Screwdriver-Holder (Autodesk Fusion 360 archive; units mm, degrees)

design "Screwdriver-Holder" references "Base"
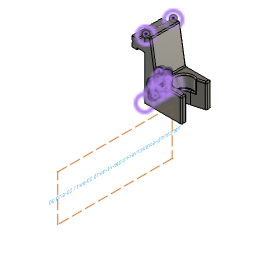
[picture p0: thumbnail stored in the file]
parameter "back_width_min" = 5
parameter "back_width_max" = 10
parameter "width" = 25 (= "screwdriver_handle_width + 10 mm")
parameter "height" = 50
parameter "bottom_height" = 10
parameter "screwdriver_handle_width" = 15
parameter "screwdriver_stick_width" = 11
parameter "pull_out_tolerance" = 3
parameter "screwdriver_inset" = 10
parameter "handle_padding" = 3
sketch "Back" plane through (0, 0, 0) normal (1, 0, 0) x axis (0, 1, 0)
  line L1 (25, 0) -> (0, 0)
  line L2 (25, 50) -> (25, 0)
  line L3 (0, 50) -> (25, 50)
  line L4 (0, 0) -> (0, 50)
  point P1 (0, 0)
  point P2 (0, 0)
  point P3 (25, 0)
  point P5 (0, 50)
  horizontal L1
  vertical L2
  horizontal L3
  vertical L4
  coincident P1 P2
  dimension "d5" distance P2 P3 = 25 (= "width")
  dimension "d6" distance P2 P5 = 50 (= "height")
extrude "Extrude1" new body sketch "Back" along normal blind 10 (= "back_width_max")
sketch "Bottom" plane through (10, 0, 0) normal (1, 0, 0) x axis (0, 1, 0)
  line L1 (0, 0) -> (0, 50)
  line L2 (25, 0) -> (0, 0)
  line L3 (25, 50) -> (25, 0)
  line L4 (0, 50) -> (25, 50)
  line L5 (25, 50) -> (25, 0)
  line L6 (25, 10) -> (25, 0)
  line L7 (25, 20) -> (25, 10)
  line L8 (0, 20) -> (25, 20)
  point P4 (25, 0)
  point P8 (25, 0)
  point P11 (0, 20)
  point P9 (25, 10)
  point P10 (25, 20)
  coincident P4 P8
  perpendicular L2 L6
  parallel L5 L7
  coincident L1 P11
  perpendicular L1 L8
  dimension "d14" distance P8 P9 = 10 (= "screwdriver_inset")
  dimension "d15" distance P9 P10 = 10 (= "bottom_height")
extrude "Extrude2" add sketch "Bottom" + "Sketch4" profile of S1:L1 S1:L2 S1:L3 S1:L5 S1:L8 blind 21 (= "screwdriver_handle_width + handle_padding + pull_out_tolerance")
sketch "Holes" plane through (0, 0, 20) normal (0, 0, 1) x axis (-1, 0, 0)
  line L1 (-10, 0) -> (-10, -25)
  line L2 (-31, 0) -> (-10, 0)
  line L3 (-31, -25) -> (-31, 0)
  line L4 (-10, -25) -> (-31, -25)
  line L5 (-31, -25) -> (-10, 0)
  line L6 (-20.5, -25) -> (-20.5, 0)
  line L7 (-31, -7) -> (-20.5, -7)
  line L8 (-31, -18) -> (-20.5, -18)
  line L9 (-31, -4) -> (-31, -7)
  line L10 (-31, -21) -> (-31, -18)
  line L11 (-31, -21) -> (-20.5, -18)
  line L12 (-31, -4) -> (-20.5, -7)
  circle C1 centre (-20.5, -12.5) radius 7.5
  circle C2 centre (-20.5, -12.5) radius 5.5
  point P3 (-10, 0)
  point P6 (-10, 0)
  point P5 (-31, -25)
  point P7 (-31, -25)
  point P8 (-20.5, -12.5)
  point P10 (-20.5, 0)
  point P11 (-20.5, -25)
  point P12 (-20.5, -7)
  point P13 (-31, -7)
  point P14 (-20.5, -18)
  point P15 (-31, -18)
  point P16 (-31, -4)
  point P17 (-31, -21)
  coincident P3 P6
  coincident P5 P7
  midpoint L5 P8
  concentric C1 C2
  midpoint L2 P10
  midpoint L4 P11
  coincident C2 P12
  coincident L6 P12
  coincident L3 P13
  tangent C2 L7
  coincident L6 P14
  coincident C2 P14
  coincident L3 P15
  tangent C2 L8
  perpendicular L7 L9
  perpendicular L8 L10
  dimension "d19" diameter C1 = 15 (= "screwdriver_handle_width")
  dimension "d20" diameter C2 = 11 (= "screwdriver_stick_width")
  dimension "d25" distance P13 P16 = 3 (= "handle_padding")
  dimension "d26" distance P15 P17 = 3 (= "handle_padding")
extrude "Extrude3" cut sketch "Holes" + "Sketch4" profile of S1:L3 S1:C1 S1:C2 S1:L7 S1:L8 blind -2000
extrude "Extrude4" cut sketch "Holes" + "Sketch4" profile of S1:C1 S1:C2 S1:L7 S1:L8 no distance stored
component_insert "Component Insert"
move "Move1" sketch "Sketch4"
move "Move3" sketch "Sketch4"
move "Move4" sketch "Sketch4"
position "Position1"
sketch "Sketch4" plane through (0, 37.5, 0) normal (0, 1, 0) x axis (-1, 0, 0)
  line L1 (-9.6118, 60) -> (-9.6118, 10)
  line L2 (-19.6118, 60) -> (-9.6118, 60)
  line L3 (-19.6118, 30) -> (-19.6118, 60)
  line L4 (-9.6118, 10) -> (-40.6118, 10)
  line L5 (-14.6118, 60) -> (-9.6118, 60)
  line L6 (-19.6118, 30) -> (-14.6118, 60)
  line L7 (-40.6118, 30) -> (-19.6118, 30)
  line L8 (-40.6118, 10) -> (-40.6118, 30)
  point P3 (-9.6118, 60)
  point P7 (-9.6118, 60)
  point P5 (-19.6118, 30)
  point P9 (-19.6118, 30)
  point P8 (-14.6118, 60)
  coincident P3 P7
  perpendicular L1 L5
  coincident P5 P9
  dimension "d27" distance P7 P8 = 5 (= "back_width_min")
extrude "Extrude5" cut sketch "Sketch4" profile of L2 L3 L6 against normal blind 1000
fillet "Fillet1" radius 1
sketch "Text" plane through (9.6118, 0, 0) normal (-1, 0, 0) x axis (0, -1, 0)
  line L1 (-37.5, 10) -> (-37.5, 59)
  line L2 (-12.5, 10) -> (-37.5, 10)
  line L3 (-12.5, 59) -> (-12.5, 10)
  line L4 (-36.5, 60) -> (-13.5, 60)
  line L5 (-37.5, 29) -> (-12.5, 29)
  line L6 (-37.5, 10) -> (-37.5, 29)
  line L7 (-12.5, 10) -> (-37.5, 10)
  line L8 (-12.5, 29) -> (-12.5, 10)
  line L9 (-12.5, 19.5) -> (-37.5, 19.5)
  curve K1
  curve K2
  curve K3
  curve K4
  arc A1 centre (-36.5, 59) radius 1 clockwise from (-37.5, 59) to (-36.5, 60)
  arc A2 centre (-13.5, 59) radius 1 clockwise from (-13.5, 60) to (-12.5, 59)
  point P4 (-37.5, 10)
  point P11 (-37.5, 10)
  point P8 (-12.5, 29)
  point P9 (-12.5, 29)
  point P13 (-37.5, 19.5)
  point P14 (-12.5, 19.5)
  horizontal L5
  vertical L6
  horizontal L7
  vertical L8
  coincident P4 P11
  coincident P8 P9
  midpoint L6 P13
  midpoint L8 P14
  coincident P8
  coincident P4
  coincident P14
  dimension "d39" Text1-Height = 3
extrude "Extrude12" cut sketch "Text" + "Sketch4" blind -2
sketch "File name" plane through (9.6118, 0, 0) normal (-1, 0, 0) x axis (0, -1, 0)
  line L1 (-37.5, 10) -> (-37.5, 59)
  line L2 (-12.5, 10) -> (-37.5, 10)
  line L3 (-12.5, 59) -> (-12.5, 10)
  curve K1
  curve K2
  curve K3
  curve K4
  line L4 (-36.5, 60) -> (-13.5, 60)
  line L5 (-26.0273, 25.0232) -> (-25.2046, 27.1965)
  line L6 (-26.3711, 25.0232) -> (-26.0273, 25.0232)
  line L7 (-27.1978, 27.1965) -> (-26.3711, 25.0232)
  line L8 (-26.809, 27.1965) -> (-27.1978, 27.1965)
  line L9 (-26.3424, 25.895) -> (-26.809, 27.1965)
  curve K5 (-26.2033, 25.457) -> (-26.3424, 25.895)
  curve K6 (-26.0662, 25.8704) -> (-26.2033, 25.457)
  line L10 (-25.5832, 27.1965) -> (-26.0662, 25.8704)
  line L11 (-25.2046, 27.1965) -> (-25.5832, 27.1965)
  line L12 (-32.3158, 20.3411) -> (-32.3158, 21.53)
  line L13 (-32.6842, 20.3411) -> (-32.3158, 20.3411)
  line L14 (-32.6842, 23.3411) -> (-32.6842, 20.3411)
  line L15 (-32.3158, 23.3411) -> (-32.6842, 23.3411)
  line L16 (-32.3158, 22.2647) -> (-32.3158, 23.3411)
  curve K7 (-31.6651, 22.5634) -> (-32.3158, 22.2647)
  curve K8 (-31.2456, 22.4673) -> (-31.6651, 22.5634)
  curve K9 (-30.9918, 22.2053) -> (-31.2456, 22.4673)
  curve K10 (-30.9141, 21.7183) -> (-30.9918, 22.2053)
  line L17 (-30.9141, 20.3411) -> (-30.9141, 21.7183)
  line L18 (-31.2824, 20.3411) -> (-30.9141, 20.3411)
  line L19 (-31.2824, 21.7183) -> (-31.2824, 20.3411)
  curve K11 (-31.4031, 22.1194) -> (-31.2824, 21.7183)
  curve K12 (-31.7408, 22.2462) -> (-31.4031, 22.1194)
  curve K13 (-32.0498, 22.1603) -> (-31.7408, 22.2462)
  curve K14 (-32.2544, 21.9311) -> (-32.0498, 22.1603)
  curve K15 (-32.3158, 21.53) -> (-32.2544, 21.9311)
  line L20 (-26.0416, 23.3533) -> (-26.279, 23.3533)
  line L21 (-26.0416, 20.3411) -> (-26.0416, 23.3533)
  line L22 (-26.41, 20.3411) -> (-26.0416, 20.3411)
  line L23 (-26.41, 22.6883) -> (-26.41, 20.3411)
  line L24 (-27.1467, 22.6003) -> (-27.1467, 22.2442)
  line L25 (-26.5276, 15.6589) -> (-26.1593, 15.6589)
  line L26 (-26.5276, 18.0061) -> (-26.5276, 15.6589)
  line L27 (-28.8155, 15.6589) -> (-28.4328, 15.6589)
  line L28 (-29.1613, 16.9604) -> (-28.8155, 15.6589)
  line L29 (-29.2452, 17.3308) -> (-29.1613, 16.9604)
  line L30 (-29.6852, 15.6589) -> (-29.2452, 17.3308)
  curve K16 (-30.8046, 13.1992) -> (-31.1238, 13.1542)
  curve K17 (-30.3564, 13.1255) -> (-30.8046, 13.1992)
  curve K18 (-31.2875, 12.0737) -> (-30.7248, 11.8977)
  curve K19 (-31.5249, 12.2804) -> (-31.2875, 12.0737)
  curve K20 (-31.6047, 12.573) -> (-31.5249, 12.2804)
  curve K21 (-31.5392, 12.8411) -> (-31.6047, 12.573)
  curve K22 (-31.3571, 13.0477) -> (-31.5392, 12.8411)
  curve K23 (-31.1238, 13.1542) -> (-31.3571, 13.0477)
  curve K24 (-21.7902, 13.9891) -> (-22.3346, 13.8131)
  curve K25 (-21.3666, 13.8909) -> (-21.7902, 13.9891)
  curve K26 (-20.8796, 13.1644) -> (-21.0658, 13.6105)
  curve K27 (-24.561, 13.6105) -> (-24.8619, 13.8909)
  curve K28 (-24.3748, 13.1644) -> (-24.561, 13.6105)
  curve K29 (-25.8298, 13.8131) -> (-26.1552, 13.3117)
  curve K30 (-25.2855, 13.9891) -> (-25.8298, 13.8131)
  curve K31 (-24.8619, 13.8909) -> (-25.2855, 13.9891)
  curve K32 (-17.6872, 18.2926) -> (-17.9881, 18.573)
  curve K33 (-17.501, 17.8465) -> (-17.6872, 18.2926)
  curve K34 (-17.4335, 17.1385) -> (-17.501, 17.8465)
  curve K35 (-17.542, 16.2851) -> (-17.4335, 17.1385)
  curve K36 (-17.8673, 15.7838) -> (-17.542, 16.2851)
  curve K37 (-18.4117, 15.6078) -> (-17.8673, 15.7838)
  curve K38 (-24.3932, 18.2701) -> (-24.9335, 17.9181)
  curve K39 (-24.0658, 18.6712) -> (-24.3932, 18.2701)
  curve K40 (-21.6122, 17.9939) -> (-21.7207, 17.1385)
  curve K41 (-21.2868, 18.4952) -> (-21.6122, 17.9939)
  curve K42 (-31.4042, 17.8076) -> (-31.8523, 17.8813)
  curve K43 (-31.1177, 17.6071) -> (-31.4042, 17.8076)
  curve K44 (-30.9908, 17.2715) -> (-31.1177, 17.6071)
  curve K45 (-31.4942, 17.4843) -> (-31.351, 17.2224)
  curve K46 (-32.1879, 17.4945) -> (-31.8257, 17.5784)
  curve K47 (-32.2964, 17.2981) -> (-32.1879, 17.4945)
  curve K48 (-32.2514, 17.1692) -> (-32.2964, 17.2981)
  curve K49 (-32.1102, 17.0709) -> (-32.2514, 17.1692)
  curve K50 (-31.7848, 16.9768) -> (-32.1102, 17.0709)
  curve K51 (-30.9969, 16.6126) -> (-31.2404, 16.8049)
  curve K52 (-30.9089, 16.2974) -> (-30.9969, 16.6126)
  curve K53 (-31.0174, 15.9495) -> (-30.9089, 16.2974)
  curve K54 (-31.3264, 15.6978) -> (-31.0174, 15.9495)
  curve K55 (-32.4314, 15.7858) -> (-31.7848, 15.6098)
  curve K56 (-32.7138, 16.3076) -> (-32.4314, 15.7858)
  curve K57 (-20.2012, 23.2551) -> (-20.6248, 23.3533)
  curve K58 (-24.0423, 22.3301) -> (-24.6091, 22.1419)
  curve K59 (-23.1091, 21.3581) -> (-23.3793, 22.058)
  curve K60 (-23.3465, 20.6542) -> (-23.1091, 21.3581)
  curve K61 (-24.1344, 20.2899) -> (-23.3465, 20.6542)
  curve K62 (-24.8035, 20.5191) -> (-24.1344, 20.2899)
  curve K63 (-21.4945, 22.676) -> (-21.603, 21.8206)
  curve K64 (-21.1692, 23.1774) -> (-21.4945, 22.676)
  curve K65 (-20.6248, 23.3533) -> (-21.1692, 23.1774)
  line L31 (-24.7115, 21.1596) -> (-25.0982, 21.1269)
  curve K66 (-24.4618, 21.9229) -> (-24.1405, 22.0048)
  line L32 (-29.5675, 20.3411) -> (-29.1276, 22.013)
  line L33 (-29.9523, 20.3411) -> (-29.5675, 20.3411)
  line L34 (-30.6173, 22.5143) -> (-29.9523, 20.3411)
  line L35 (-30.2367, 22.5143) -> (-30.6173, 22.5143)
  line L36 (-29.8909, 21.2599) -> (-30.2367, 22.5143)
  line L37 (-29.7619, 20.7933) -> (-29.8909, 21.2599)
  curve K67 (-29.6494, 21.2415) -> (-29.7619, 20.7933)
  line L38 (-29.3035, 22.5143) -> (-29.6494, 21.2415)
  line L39 (-28.925, 22.5143) -> (-29.3035, 22.5143)
  line L40 (-28.5996, 21.2538) -> (-28.925, 22.5143)
  line L41 (-28.4911, 20.8383) -> (-28.5996, 21.2538)
  line L42 (-28.3663, 21.2578) -> (-28.4911, 20.8383)
  line L43 (-27.9939, 22.5143) -> (-28.3663, 21.2578)
  line L44 (-27.6357, 22.5143) -> (-27.9939, 22.5143)
  line L45 (-28.3151, 20.3411) -> (-27.6357, 22.5143)
  line L46 (-28.6978, 20.3411) -> (-28.3151, 20.3411)
  line L47 (-29.0437, 21.6426) -> (-28.6978, 20.3411)
  line L48 (-29.1276, 22.013) -> (-29.0437, 21.6426)
  line L49 (-23.5941, 28.0355) -> (-23.8315, 28.0355)
  line L50 (-23.5941, 25.0232) -> (-23.5941, 28.0355)
  line L51 (-23.9625, 25.0232) -> (-23.5941, 25.0232)
  line L52 (-23.9625, 27.3704) -> (-23.9625, 25.0232)
  curve K68 (-24.3124, 27.1166) -> (-23.9625, 27.3704)
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  dimension "d57" Text1-Height = 3
extrude "Extrude17" new body of existing geometry blind 1
extrude "Extrude18" add sketch "Sketch4" to an object
extrude "Extrude21" cut sketch "Sketch4" to an object
extrude "Extrude22" add sketch "Sketch4" to an object
extrude "Extrude24" cut sketch "Sketch4" to an object
extrude "Extrude25" add sketch "Sketch4" to an object
extrude "Extrude26" cut sketch "Sketch4" to an object

design "Base"
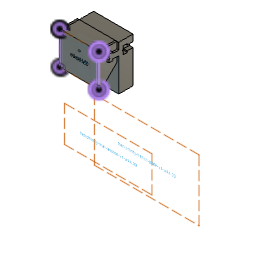
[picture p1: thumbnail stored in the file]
parameter "wall_anchor_height" = 60
parameter "wall_anchor_width" = 20
parameter "wall_anchor_angle" = 45
parameter "width_per_slot" = 40
parameter "slot_inner_width" = 8.5
parameter "slot_inner_height" = 4.5
parameter "slot_outer_width" = 5.6
parameter "slot_outer_height" = 6.5
parameter "slot_dept" = 15
parameter "print_tolerance" = 0.12
parameter "base_plate_thickness" = 16
parameter "base_plate_slot_height" = 50
parameter "wall_anchor_angle_rounded_border" = 1.5
parameter "base_plate_screw_hole_diameter" = 4
parameter "base_plate_screw_head_diameter" = 8
parameter "base_plate_screw_head_height" = 4
parameter "base_plate_screw_hole_side_distance" = 7
parameter "slot_screw_head_width" = 4.42 (= "4.3 mm + print_tolerance")
parameter "slot_screw_thread_width" = 2.12 (= "2 mm + print_tolerance")
parameter "slot_screw_head_height" = 2.12 (= "2 mm + print_tolerance")
parameter "width" = 44
parameter "filament_hole_width" = 1.7
sketch "Side" plane through (0, 0, 0) normal (1, 0, 0) x axis (0, 1, 0)
  line L1 (39.6118, 0) -> (19.6118, 0)
  line L2 (39.6118, 60) -> (39.6118, 0)
  line L3 (19.6118, 60) -> (39.6118, 60)
  line L4 (19.6118, 0) -> (19.6118, 60)
  line L5 (39.6118, 39.6118) -> (0, 0)
  line L6 (56.0196, 0) -> (0, 0)
  point P1 (0, 0)
  point P6 (0, 0)
  point P7 (39.6118, 39.6118)
  point P2 (19.6118, 0)
  point P3 (39.6118, 0)
  point P5 (19.6118, 60)
  horizontal L1
  vertical L2
  horizontal L3
  vertical L4
  horizontal L6
  coincident P1 P6
  coincident L2 P7
  dimension "d4" distance P2 P3 = 20 (= "wall_anchor_width")
  dimension "d5" distance P2 P5 = 60 (= "wall_anchor_height")
  dimension "d6" angle L5 L6 = 45 (= "wall_anchor_angle")
extrude "Extrude1" new body sketch "Side" profile of L1 L2 L3 L4 L5 along normal blind 40 (= "width_per_slot")
sketch "Slot LeftToRight" plane through (0, 0, 0) normal (-1, 0, 0) x axis (0, -1, 0)
  line L1 (-19.6118, 60) -> (-19.6118, 19.6118)
  line L2 (-39.6118, 60) -> (-19.6118, 60)
  line L3 (-39.6118, 39.6118) -> (-39.6118, 60)
  line L4 (-19.6118, 19.6118) -> (-39.6118, 39.6118)
  line L5 (-39.6118, 52.6059) -> (-39.6118, 49.8059)
  line L6 (-39.6118, 47.0059) -> (-39.6118, 49.8059)
  line L7 (-33.1118, 52.6059) -> (-39.6118, 52.6059)
  line L8 (-28.6118, 49.8059) -> (-39.6118, 49.8059)
  line L9 (-28.6118, 54.0559) -> (-28.6118, 49.8059)
  line L10 (-33.1118, 54.0559) -> (-28.6118, 54.0559)
  line L11 (-33.1118, 52.6059) -> (-33.1118, 54.0559)
  line L12 (-28.6118, 45.5559) -> (-28.6118, 49.8059)
  line L13 (-33.1118, 45.5559) -> (-28.6118, 45.5559)
  line L14 (-33.1118, 47.0059) -> (-33.1118, 45.5559)
  line L15 (-33.1118, 47.0059) -> (-39.6118, 47.0059)
  point P6 (-39.6118, 49.8059)
  point P7 (-39.6118, 52.6059)
  point P17 (-39.6118, 47.0059)
  point P9 (-33.1118, 52.6059)
  point P16 (-33.1118, 47.0059)
  point P10 (-28.6118, 49.8059)
  point P13 (-28.6118, 49.8059)
  point P11 (-28.6118, 54.0559)
  point P14 (-28.6118, 45.5559)
  point P12 (-33.1118, 54.0559)
  point P15 (-33.1118, 45.5559)
  midpoint L3 P6
  parallel L3 L5
  parallel L3 L6
  perpendicular L3 L7
  perpendicular L6 L8
  perpendicular L8 L9
  perpendicular L9 L10
  symmetric P7 L8 P17
  symmetric P9 L8 P16
  symmetric P10 L8 P13
  symmetric L8 P11 P14
  symmetric L8 P12 P15
  dimension "d80" distance P6 P7 = 2.8 (= "slot_outer_width / 2")
  dimension "d82" distance P7 P9 = 6.5 (= "slot_outer_height")
  dimension "d84" distance P6 P10 = 11 (= "slot_outer_height + slot_inner_height")
  dimension "d85" distance P10 P11 = 4.25 (= "slot_inner_width / 2")
  dimension "d86" distance P11 P12 = 4.5 (= "slot_inner_height")
extrude "Extrude3" cut sketch "Slot LeftToRight" profile of L3 L5 L6 L7 L9 L10 L11 L12 L13 L14 L15 against normal blind 40 (magnitude of "width_per_slot * -1")
sketch "Plate" plane through (0, 39.6118, 0) normal (0, 1, 0) x axis (-1, 0, 0)
  line L1 (0, 39.6118) -> (-40, 39.6118)
  line L2 (-40, 60) -> (0, 60)
  line L3 (0, 10) -> (0, 60)
  line L4 (-40, 10) -> (-40, 60)
  line L5 (-40, 10) -> (0, 10)
  line L6 (-40, 47.0059) -> (0, 47.0059)
  line L7 (-40, 52.6059) -> (-40, 60)
  line L8 (0, 60) -> (0, 52.6059)
  line L9 (0, 52.6059) -> (-40, 52.6059)
  line L10 (-40, 60) -> (0, 60)
  line L11 (-40, 39.6118) -> (-40, 47.0059)
  line L12 (0, 47.0059) -> (0, 39.6118)
  point P2 (0, 60)
  point P3 (-40, 60)
  point P4 (0, 10)
  point P5 (-40, 10)
  perpendicular L1 L3
  perpendicular L1 L4
  dimension "d36" distance P2 P3 = 40 (= "width_per_slot")
  dimension "d37" distance P2 P4 = 50 (= "base_plate_slot_height")
  dimension "d39" distance P3 P5 = 50 (= "base_plate_slot_height")
extrude "Extrude6" new body sketch "Plate" profile of L1 L2 L3 L4 L5 L6 L7 L8 L9 L10 along normal blind 16 (= "base_plate_thickness") bodies "Base plate with slot"
sketch "Slot" plane through (0, 0, 0) normal (-1, 0, 0) x axis (0, -1, 0)
  line L1 (-19.6118, 60) -> (-19.6118, 19.6118)
  line L2 (-39.6118, 60) -> (-19.6118, 60)
  line L3 (-39.6118, 52.6059) -> (-39.6118, 60)
  line L4 (-33.1118, 52.6059) -> (-39.6118, 52.6059)
  line L5 (-33.1118, 54.0559) -> (-33.1118, 52.6059)
  line L6 (-28.6118, 54.0559) -> (-33.1118, 54.0559)
  line L7 (-28.6118, 45.5559) -> (-28.6118, 54.0559)
  line L8 (-33.1118, 45.5559) -> (-28.6118, 45.5559)
  line L9 (-33.1118, 47.0059) -> (-33.1118, 45.5559)
  line L10 (-39.6118, 47.0059) -> (-33.1118, 47.0059)
  line L11 (-39.6118, 39.6118) -> (-39.6118, 47.0059)
  line L12 (-19.6118, 19.6118) -> (-39.6118, 39.6118)
  line L13 (-33.1118, 52.6059) -> (-39.6118, 52.6059)
  line L14 (-33.1118, 54.0559) -> (-33.1118, 52.6059)
  line L15 (-28.6118, 54.0559) -> (-33.1118, 54.0559)
  line L16 (-28.6118, 45.5559) -> (-28.6118, 54.0559)
  line L17 (-33.1118, 45.5559) -> (-28.6118, 45.5559)
  line L18 (-33.1118, 47.0059) -> (-33.1118, 45.5559)
  line L19 (-39.6118, 47.0059) -> (-33.1118, 47.0059)
  line L20 (-39.6118, 10) -> (-39.6118, 60)
  line L21 (-32.9918, 52.4859) -> (-39.6118, 52.4859)
  line L22 (-32.9918, 53.9359) -> (-32.9918, 52.4859)
  line L23 (-28.7318, 53.9359) -> (-32.9918, 53.9359)
  line L24 (-28.7318, 45.6759) -> (-28.7318, 53.9359)
  line L25 (-32.9918, 45.6759) -> (-28.7318, 45.6759)
  line L26 (-32.9918, 47.1259) -> (-32.9918, 45.6759)
  line L27 (-39.6118, 47.1259) -> (-32.9918, 47.1259)
  line L28 (-33.1118, 52.6059) -> (-39.6118, 52.6059)
  line L29 (-33.1118, 52.6059) -> (-33.1118, 54.0559)
  line L30 (-28.6118, 54.0559) -> (-33.1118, 54.0559)
  line L31 (-28.6118, 45.5559) -> (-28.6118, 54.0559)
  line L32 (-33.1118, 45.5559) -> (-28.6118, 45.5559)
  line L33 (-33.1118, 47.0059) -> (-33.1118, 45.5559)
  line L34 (-39.6118, 47.0059) -> (-33.1118, 47.0059)
  line L35 (-39.6118, 47.0059) -> (-39.6118, 52.6059)
  line L36 (-49.1118, 52.6059) -> (-55.6118, 52.6059)
  line L37 (-49.1118, 52.6059) -> (-49.1118, 54.0559)
  line L38 (-44.6118, 54.0559) -> (-49.1118, 54.0559)
  line L39 (-44.6118, 45.5559) -> (-44.6118, 54.0559)
  line L40 (-49.1118, 45.5559) -> (-44.6118, 45.5559)
  line L41 (-49.1118, 47.0059) -> (-49.1118, 45.5559)
  line L42 (-55.6118, 47.0059) -> (-49.1118, 47.0059)
  line L43 (-55.6118, 47.0059) -> (-55.6118, 52.6059)
  point P15 (-39.6118, 52.6059)
  point P33 (-39.6118, 52.6059)
  point P16 (-33.1118, 52.6059)
  point P34 (-33.1118, 52.6059)
  point P17 (-33.1118, 54.0559)
  point P35 (-33.1118, 54.0559)
  point P36 (-33.1118, 52.6059)
  point P18 (-28.6118, 54.0559)
  point P37 (-28.6118, 54.0559)
  point P19 (-28.6118, 45.5559)
  point P38 (-28.6118, 45.5559)
  point P10 (-28.6118, 45.5559)
  point P39 (-28.6118, 45.5559)
  point P11 (-33.1118, 45.5559)
  point P40 (-33.1118, 45.5559)
  point P41 (-33.1118, 45.5559)
  point P12 (-33.1118, 47.0059)
  point P42 (-33.1118, 47.0059)
  point P21 (-33.1118, 47.0059)
  point P43 (-33.1118, 47.0059)
  point P22 (-39.6118, 47.0059)
  point P44 (-39.6118, 47.0059)
  point P45 (-39.6118, 52.6059)
  point P46 (-39.6118, 47.0059)
  coincident P15 P33
  coincident P16 P34
  coincident P17 P35
  coincident P16 P36
  coincident P18 P37
  coincident P19 P38
  coincident P10 P39
  coincident P11 P40
  coincident P11 P41
  coincident P12 P42
  coincident P21 P43
  coincident P22 P44
  coincident P15 P45
  coincident P22 P46
  dimension "d91" = 0.12 (= "print_tolerance")
  dimension "d96" R-Pattern1-uDistance = -16 (= "base_plate_thickness * -1")
  dimension "d97" R-Pattern1-vDistance = 0
extrude "Extrude7" add sketch "Slot" profile of L20 L24 L23 L27 L22 L25 L26 L21 against normal blind 40 (magnitude of "width_per_slot * -1")
extrude "Extrude8" cut sketch "Slot" profile of L36 L37 L38 L39 L40 L41 L42 L43 no distance stored
sketch "Sketch3" plane through (0, 0, 0) normal (-1, 0, 0) x axis (0, -1, 0)
  line L1 (-32.9918, 47.1259) -> (-39.6118, 47.1259)
  line L2 (-32.9918, 45.6759) -> (-32.9918, 47.1259)
  line L3 (-28.7318, 45.6759) -> (-32.9918, 45.6759)
  line L4 (-28.7318, 53.9359) -> (-28.7318, 45.6759)
  line L5 (-32.9918, 53.9359) -> (-28.7318, 53.9359)
  line L6 (-32.9918, 52.4859) -> (-32.9918, 53.9359)
  line L7 (-39.6118, 52.4859) -> (-32.9918, 52.4859)
  line L8 (-44.6118, 45.5559) -> (-44.6118, 54.0559)
  line L9 (-32.9918, 52.4859) -> (-39.6118, 52.4859)
  line L10 (-32.9918, 53.9359) -> (-32.9918, 52.4859)
  line L11 (-28.7318, 53.9359) -> (-32.9918, 53.9359)
  line L12 (-28.7318, 45.6759) -> (-28.7318, 53.9359)
  line L13 (-32.9918, 45.6759) -> (-28.7318, 45.6759)
  line L14 (-32.9918, 47.1259) -> (-32.9918, 45.6759)
  line L15 (-39.6118, 47.1259) -> (-32.9918, 47.1259)
  line L16 (-39.6118, 47.1259) -> (-39.6118, 52.4859)
  line L17 (-55.6118, 52.4859) -> (-48.9918, 52.4859)
  line L18 (-48.9918, 52.4859) -> (-48.9918, 53.9359)
  line L19 (-48.9918, 53.9359) -> (-44.7318, 53.9359)
  line L20 (-44.7318, 45.6759) -> (-44.7318, 53.9359)
  line L21 (-48.9918, 45.6759) -> (-44.7318, 45.6759)
  line L22 (-48.9918, 47.1259) -> (-48.9918, 45.6759)
  line L23 (-55.6118, 47.1259) -> (-48.9918, 47.1259)
  line L24 (-55.6118, 47.1259) -> (-55.6118, 52.4859)
  line L25 (-55.6118, 47.0059) -> (-49.1118, 47.0059)
  line L26 (-55.6118, 10) -> (-55.6118, 47.0059)
  line L27 (-39.6118, 10) -> (-55.6118, 10)
  line L28 (-39.6118, 47.1259) -> (-39.6118, 10)
  line L29 (-39.6118, 60) -> (-39.6118, 52.4859)
  line L30 (-55.6118, 60) -> (-39.6118, 60)
  line L31 (-55.6118, 52.6059) -> (-55.6118, 60)
  line L32 (-49.1118, 52.6059) -> (-55.6118, 52.6059)
  line L33 (-49.1118, 54.0559) -> (-49.1118, 52.6059)
  line L34 (-44.6118, 54.0559) -> (-49.1118, 54.0559)
  line L35 (-49.1118, 45.5559) -> (-44.6118, 45.5559)
  line L36 (-49.1118, 47.0059) -> (-49.1118, 45.5559)
  point P9 (-39.6118, 52.4859)
  point P20 (-39.6118, 52.4859)
  point P19 (-39.6118, 47.1259)
  point P21 (-39.6118, 47.1259)
  coincident P9 P20
  coincident P19 P21
  dimension "d105" R-Pattern1-vDistance = 0
extrude "Extrude3" new body sketch "Sketch3" profile of L17 L18 L19 L20 L21 L22 L23 L24 against normal blind 40 (magnitude of "width_per_slot * -1")
sketch "Screw hole" plane through (0, 28.6118, 0) normal (0, 1, 0) x axis (-1, 0, 0)
  line L1 (0, 54.0559) -> (0, 45.5559)
  line L2 (-40, 54.0559) -> (0, 54.0559)
  line L3 (-40, 45.5559) -> (-40, 54.0559)
  line L4 (0, 45.5559) -> (-40, 45.5559)
  line L5 (0, 45.5559) -> (-40, 54.0559)
  line L6 (-40, 45.5559) -> (0, 54.0559)
  circle C1 centre (-20, 49.8059) radius 2.21
  circle C2 centre (-20, 49.8059) radius 1.06
  point P4 (-40, 54.0559)
  point P6 (-40, 54.0559)
  point P2 (0, 45.5559)
  point P7 (0, 45.5559)
  point P3 (0, 54.0559)
  point P8 (0, 54.0559)
  point P5 (-40, 45.5559)
  point P9 (-40, 45.5559)
  point P10 (-20, 49.8059)
  coincident P4 P6
  coincident P2 P7
  coincident P3 P8
  coincident P5 P9
  midpoint L5 P10
  concentric C1 C2
  dimension "d119" diameter C1 = 4.42 (= "slot_screw_head_width")
  dimension "d120" diameter C2 = 2.12 (= "slot_screw_thread_width")
extrude "Extrude4" cut sketch "Screw hole" profile of C2 against normal blind 2000
extrude "Extrude5" cut sketch "Screw hole" profile of C1 C2 no distance stored
fillet "Fillet1" radius 1.5 (= "wall_anchor_angle_rounded_border")
work_plane "WorkPlane1" sketch "Slot LeftToRight" AlongDistance -20 (= "-width_per_slot / 2")
sketch "Screw head" plane through (20, 0, 0) normal (-1, 0, 0) x axis (0, -1, 0)
  line L1 (-28.6118, 52.0159) -> (-28.6118, 47.5959)
  line L2 (-26.4918, 52.0159) -> (-26.4918, 47.5959)
  line L3 (-26.4918, 48.7459) -> (-26.4918, 50.8659)
  line L4 (-26.4918, 50.8659) -> (-28.6118, 52.0159)
  line L5 (-26.4918, 52.0159) -> (-28.6118, 52.0159)
  point P3 (-28.6118, 52.0159)
  point P8 (-28.6118, 52.0159)
  point P6 (-26.4918, 50.8659)
  point P9 (-26.4918, 50.8659)
  point P10 (-28.6118, 52.0159)
  point P5 (-26.4918, 52.0159)
  point P11 (-26.4918, 52.0159)
  coincident P3 P8
  coincident P6 P9
  coincident P3 P10
  coincident P5 P11
revolve "Revolve1" sketch "Screw head" AlongAngle 360
sketch "Plate" plane through (0, 39.6118, 0) normal (0, 1, 0) x axis (-1, 0, 0)
  line L1 (0, 39.6118) -> (-40, 39.6118)
  line L2 (-40, 60) -> (0, 60)
  line L3 (0, 10) -> (0, 60)
  line L4 (-40, 10) -> (-40, 60)
  line L5 (-40, 10) -> (0, 10)
  line L6 (-40, 47.0059) -> (0, 47.0059)
  line L7 (-40, 39.6118) -> (-40, 47.0059)
  line L8 (0, 47.0059) -> (0, 39.6118)
  line L9 (0, 52.6059) -> (-40, 52.6059)
  line L10 (-40, 60) -> (0, 60)
  line L11 (0, 60) -> (0, 52.6059)
  line L12 (-40, 52.6059) -> (-40, 60)
  point P2 (0, 60)
  point P3 (-40, 60)
  point P4 (0, 10)
  point P5 (-40, 10)
  perpendicular L1 L3
  perpendicular L1 L4
  dimension "d36_1" distance P2 P3 = 40 (= "width_per_slot")
  dimension "d37_1" distance P2 P4 = 50 (= "base_plate_slot_height")
  dimension "d39_1" distance P3 P5 = 50 (= "base_plate_slot_height")
extrude "Extrude6" new body sketch "Plate" profile of L1 L2 L3 L4 L5 L6 L7 L8 L9 L10 along normal blind 16 (= "base_plate_thickness") named "d89_1" bodies "Base plate with slot"
sketch "Slot" plane through (0, 0, 0) normal (-1, 0, 0) x axis (0, -1, 0)
  line L1 (-19.6118, 60) -> (-19.6118, 23.2332)
  line L2 (-39.6118, 60) -> (-19.6118, 60)
  line L3 (-39.6118, 52.6059) -> (-39.6118, 60)
  line L4 (-33.1118, 52.6059) -> (-39.6118, 52.6059)
  line L5 (-33.1118, 54.0559) -> (-33.1118, 52.6059)
  line L6 (-28.6118, 54.0559) -> (-33.1118, 54.0559)
  line L7 (-28.6118, 45.5559) -> (-28.6118, 54.0559)
  line L8 (-33.1118, 45.5559) -> (-28.6118, 45.5559)
  line L9 (-33.1118, 47.0059) -> (-33.1118, 45.5559)
  line L10 (-39.6118, 47.0059) -> (-33.1118, 47.0059)
  line L11 (-39.6118, 39.6118) -> (-39.6118, 47.0059)
  line L12 (-22.1725, 22.1725) -> (-39.6118, 39.6118)
  line L13 (-33.1118, 52.6059) -> (-39.6118, 52.6059)
  line L14 (-33.1118, 54.0559) -> (-33.1118, 52.6059)
  line L15 (-28.6118, 54.0559) -> (-33.1118, 54.0559)
  line L16 (-28.6118, 45.5559) -> (-28.6118, 54.0559)
  line L17 (-33.1118, 45.5559) -> (-28.6118, 45.5559)
  line L18 (-33.1118, 47.0059) -> (-33.1118, 45.5559)
  line L19 (-39.6118, 47.0059) -> (-33.1118, 47.0059)
  line L20 (-39.6118, 10) -> (-39.6118, 60)
  line L21 (-32.9918, 52.4859) -> (-39.6118, 52.4859)
  line L22 (-32.9918, 53.9359) -> (-32.9918, 52.4859)
  line L23 (-28.7318, 53.9359) -> (-32.9918, 53.9359)
  line L24 (-28.7318, 45.6759) -> (-28.7318, 53.9359)
  line L25 (-32.9918, 45.6759) -> (-28.7318, 45.6759)
  line L26 (-32.9918, 47.1259) -> (-32.9918, 45.6759)
  line L27 (-39.6118, 47.1259) -> (-32.9918, 47.1259)
  line L28 (-33.1118, 52.6059) -> (-39.6118, 52.6059)
  line L29 (-33.1118, 52.6059) -> (-33.1118, 54.0559)
  line L30 (-28.6118, 54.0559) -> (-33.1118, 54.0559)
  line L31 (-28.6118, 45.5559) -> (-28.6118, 54.0559)
  line L32 (-33.1118, 45.5559) -> (-28.6118, 45.5559)
  line L33 (-33.1118, 47.0059) -> (-33.1118, 45.5559)
  line L34 (-39.6118, 47.0059) -> (-33.1118, 47.0059)
  line L35 (-39.6118, 47.0059) -> (-39.6118, 52.6059)
  line L36 (-49.1118, 52.6059) -> (-55.6118, 52.6059)
  line L37 (-49.1118, 52.6059) -> (-49.1118, 54.0559)
  line L38 (-44.6118, 54.0559) -> (-49.1118, 54.0559)
  line L39 (-44.6118, 45.5559) -> (-44.6118, 54.0559)
  line L40 (-49.1118, 45.5559) -> (-44.6118, 45.5559)
  line L41 (-49.1118, 47.0059) -> (-49.1118, 45.5559)
  line L42 (-55.6118, 47.0059) -> (-49.1118, 47.0059)
  line L43 (-55.6118, 47.0059) -> (-55.6118, 52.6059)
  arc A1 centre (-21.1118, 23.2332) radius 1.5 clockwise from (-19.6118, 23.2332) to (-22.1725, 22.1725)
  point P15 (-39.6118, 52.6059)
  point P33 (-39.6118, 52.6059)
  point P16 (-33.1118, 52.6059)
  point P34 (-33.1118, 52.6059)
  point P17 (-33.1118, 54.0559)
  point P35 (-33.1118, 54.0559)
  point P36 (-33.1118, 52.6059)
  point P18 (-28.6118, 54.0559)
  point P37 (-28.6118, 54.0559)
  point P19 (-28.6118, 45.5559)
  point P38 (-28.6118, 45.5559)
  point P10 (-28.6118, 45.5559)
  point P39 (-28.6118, 45.5559)
  point P11 (-33.1118, 45.5559)
  point P40 (-33.1118, 45.5559)
  point P41 (-33.1118, 45.5559)
  point P12 (-33.1118, 47.0059)
  point P42 (-33.1118, 47.0059)
  point P21 (-33.1118, 47.0059)
  point P43 (-33.1118, 47.0059)
  point P22 (-39.6118, 47.0059)
  point P44 (-39.6118, 47.0059)
  point P45 (-39.6118, 52.6059)
  point P46 (-39.6118, 47.0059)
  coincident P15 P33
  coincident P16 P34
  coincident P17 P35
  coincident P16 P36
  coincident P18 P37
  coincident P19 P38
  coincident P10 P39
  coincident P11 P40
  coincident P11 P41
  coincident P12 P42
  coincident P21 P43
  coincident P22 P44
  coincident P15 P45
  coincident P22 P46
  dimension "d91_1" = 0.12 (= "print_tolerance")
  dimension "d96_1" R-Pattern1-uDistance = -16 (= "base_plate_thickness * -1")
  dimension "d97_1" R-Pattern1-vDistance = 0
extrude "Extrude8" cut sketch "Slot" profile of L36 L37 L38 L39 L40 L41 L42 L43 no distance stored
sketch "Screw" plane through (0, 55.6118, 0) normal (0, 1, 0) x axis (-1, 0, 0)
  line L1 (-40, 47.0059) -> (0, 47.0059)
  line L2 (-40, 10) -> (-40, 47.0059)
  line L3 (0, 10) -> (-40, 10)
  line L4 (0, 47.0059) -> (0, 10)
  line L5 (-33, 17) -> (-33, 40.0059)
  line L6 (-7, 17) -> (-33, 17)
  line L7 (-7, 40.0059) -> (-7, 17)
  line L8 (-33, 40.0059) -> (-7, 40.0059)
  circle C1 centre (-33, 17) radius 4
  circle C2 centre (-33, 17) radius 2
  point P7 (-33, 17)
  point P10 (-33, 17)
  coincident P7 P10
  concentric C1 C2
  dimension "d127" = -7 (= "base_plate_screw_hole_side_distance * -1")
  dimension "d128" diameter C1 = 8
  dimension "d129" diameter C2 = 4
rectangular_pattern "R-Pattern2" countU 1 (= "floor(( width / mm ) / ( width_per_slot / cm * 10 ))") uSpaceDistance 40 (= "width_per_slot") vSpaceDistance 0
work_plane "WorkPlane2"
extrude "Extrude12" new body of existing geometry no distance stored
mirror "Mirror3" mirrorStitchTolerance 0.1
sketch "filename" plane through (0, 19.6118, 0) normal (0, -1, 0) x axis (1, 0, 0)
  dimension "d216" = 3
sketch "Sketch14" plane through (0, 19.6118, 0) normal (0, -1, 0) x axis (1, 0, 0)
  line L1 (42, 60) -> (42, 23.2332)
  line L2 (40, 23.2332) -> (40, 60)
  line L3 (42, 23.2332) -> (40, 23.2332)
  line L4 (42, 60) -> (42, 23.2332)
  line L5 (40, 60) -> (42, 60)
  line L6 (0, 60) -> (0, 23.2332)
  line L7 (-2, 60) -> (0, 60)
  line L8 (-2, 23.2332) -> (-2, 60)
  line L9 (0, 23.2332) -> (-2, 23.2332)
  curve K1
  curve K2
  curve K3
  curve K4
  point P4 (42, 23.2332)
  point P2 (-2, 60)
  coincident P4
  coincident P2
  dimension "d229" Text1-Height = 3
extrude "Extrude19" cut sketch "Sketch14" against normal blind 2
extrude "Extrude14" cut of existing geometry blind 2 (= "( width_per_slot - width ) / -2")
extrude "Extrude15" cut of existing geometry blind 2 (= "( width_per_slot - width ) / -2")
extrude "Extrude9" cut of existing geometry blind -39 (= "-width_per_slot + 1 mm")
extrude "Extrude10" add of existing geometry blind 43 (= "width - 1 mm")
sketch "Sketch7" plane through (0, 39.6118, 0) normal (0, -1, 0) x axis (1, 0, 0)
  dimension "d236" = 3
extrude "Extrude11" cut sketch "Sketch7" against normal blind 2
sketch "Sketch8" plane through (0, 39.6118, 0) normal (0, -1, 0) x axis (1, 0, 0)
  line L1 (16.0624, 30.0752) -> (15.825, 30.0752)
  line L2 (16.0624, 27.063) -> (16.0624, 30.0752)
  line L3 (15.6941, 27.063) -> (16.0624, 27.063)
  line L4 (15.6941, 29.4102) -> (15.6941, 27.063)
  curve K1 (15.3441, 29.1564) -> (15.6941, 29.4102)
  curve K2 (14.9574, 28.9661) -> (15.3441, 29.1564)
  line L5 (14.9574, 29.3222) -> (14.9574, 28.9661)
  curve K3 (15.4976, 29.6741) -> (14.9574, 29.3222)
  curve K4 (15.825, 30.0752) -> (15.4976, 29.6741)
  line L6 (19.2896, 27.063) -> (19.7295, 28.7349)
  line L7 (18.9048, 27.063) -> (19.2896, 27.063)
  line L8 (18.2398, 29.2362) -> (18.9048, 27.063)
  line L9 (18.6204, 29.2362) -> (18.2398, 29.2362)
  line L10 (18.9662, 27.9818) -> (18.6204, 29.2362)
  line L11 (19.0952, 27.5152) -> (18.9662, 27.9818)
  curve K5 (19.2077, 27.9634) -> (19.0952, 27.5152)
  line L12 (19.5535, 29.2362) -> (19.2077, 27.9634)
  line L13 (19.9321, 29.2362) -> (19.5535, 29.2362)
  line L14 (20.2575, 27.9756) -> (19.9321, 29.2362)
  line L15 (20.366, 27.5602) -> (20.2575, 27.9756)
  line L16 (20.4908, 27.9797) -> (20.366, 27.5602)
  line L17 (20.8632, 29.2362) -> (20.4908, 27.9797)
  line L18 (21.2213, 29.2362) -> (20.8632, 29.2362)
  line L19 (20.5419, 27.063) -> (21.2213, 29.2362)
  line L20 (20.1593, 27.063) -> (20.5419, 27.063)
  line L21 (19.8134, 28.3645) -> (20.1593, 27.063)
  line L22 (19.7295, 28.7349) -> (19.8134, 28.3645)
  line L23 (22.9771, 27.063) -> (22.9771, 27.7812)
  line L24 (22.6088, 27.063) -> (22.9771, 27.063)
  line L25 (22.6088, 27.7812) -> (22.6088, 27.063)
  line L26 (21.3073, 27.7812) -> (22.6088, 27.7812)
  line L27 (21.3073, 28.1189) -> (21.3073, 27.7812)
  line L28 (22.6763, 30.063) -> (21.3073, 28.1189)
  line L29 (22.9771, 30.063) -> (22.6763, 30.063)
  line L30 (22.9771, 28.1189) -> (22.9771, 30.063)
  line L31 (23.3823, 28.1189) -> (22.9771, 28.1189)
  line L32 (23.3823, 27.7812) -> (23.3823, 28.1189)
  line L33 (22.9771, 27.7812) -> (23.3823, 27.7812)
  line L34 (26.7159, 27.063) -> (26.7159, 27.4825)
  line L35 (26.2964, 27.063) -> (26.7159, 27.063)
  line L36 (26.2964, 27.4825) -> (26.2964, 27.063)
  line L37 (26.7159, 27.4825) -> (26.2964, 27.4825)
  curve K6 (27.5508, 27.3228) -> (28.2323, 27.0118)
  curve K7 (27.2541, 28.5425) -> (27.5508, 27.3228)
  curve K8 (27.3626, 29.3979) -> (27.2541, 28.5425)
  curve K9 (27.6879, 29.8992) -> (27.3626, 29.3979)
  curve K10 (28.2323, 30.0752) -> (27.6879, 29.8992)
  curve K11 (28.6559, 29.977) -> (28.2323, 30.0752)
  curve K12 (28.9567, 29.6967) -> (28.6559, 29.977)
  curve K13 (29.1429, 29.2505) -> (28.9567, 29.6967)
  curve K14 (29.2104, 28.5425) -> (29.1429, 29.2505)
  curve K15 (29.102, 27.6892) -> (29.2104, 28.5425)
  curve K16 (28.7766, 27.1878) -> (29.102, 27.6892)
  curve K17 (28.2323, 27.0118) -> (28.7766, 27.1878)
  line L38 (25.308, 27.063) -> (25.308, 27.7812)
  line L39 (24.9396, 27.063) -> (25.308, 27.063)
  line L40 (24.9396, 27.7812) -> (24.9396, 27.063)
  line L41 (23.6381, 27.7812) -> (24.9396, 27.7812)
  line L42 (23.6381, 28.1189) -> (23.6381, 27.7812)
  line L43 (25.0072, 30.063) -> (23.6381, 28.1189)
  line L44 (25.308, 30.063) -> (25.0072, 30.063)
  line L45 (25.308, 28.1189) -> (25.308, 30.063)
  line L46 (25.7132, 28.1189) -> (25.308, 28.1189)
  line L47 (25.7132, 27.7812) -> (25.7132, 28.1189)
  line L48 (25.308, 27.7812) -> (25.7132, 27.7812)
  curve K18 (29.8816, 27.3228) -> (30.5631, 27.0118)
  curve K19 (29.5849, 28.5425) -> (29.8816, 27.3228)
  curve K20 (29.6934, 29.3979) -> (29.5849, 28.5425)
  curve K21 (30.0188, 29.8992) -> (29.6934, 29.3979)
  curve K22 (30.5631, 30.0752) -> (30.0188, 29.8992)
  curve K23 (30.9867, 29.977) -> (30.5631, 30.0752)
  curve K24 (31.2875, 29.6967) -> (30.9867, 29.977)
  curve K25 (31.4737, 29.2505) -> (31.2875, 29.6967)
  curve K26 (31.5413, 28.5425) -> (31.4737, 29.2505)
  curve K27 (31.4328, 27.6892) -> (31.5413, 28.5425)
  curve K28 (31.1074, 27.1878) -> (31.4328, 27.6892)
  curve K29 (30.5631, 27.0118) -> (31.1074, 27.1878)
  line L49 (18.0965, 27.9634) -> (18.0965, 28.3338)
  line L50 (16.9649, 27.9634) -> (18.0965, 27.9634)
  line L51 (16.9649, 28.3338) -> (16.9649, 27.9634)
  line L52 (18.0965, 28.3338) -> (16.9649, 28.3338)
  line L53 (13.6293, 27.063) -> (14.4519, 29.2362)
  line L54 (13.2855, 27.063) -> (13.6293, 27.063)
  line L55 (12.4587, 29.2362) -> (13.2855, 27.063)
  line L56 (12.8475, 29.2362) -> (12.4587, 29.2362)
  line L57 (13.3141, 27.9347) -> (12.8475, 29.2362)
  curve K30 (13.4533, 27.4968) -> (13.3141, 27.9347)
  curve K31 (13.5904, 27.9102) -> (13.4533, 27.4968)
  line L58 (14.0733, 29.2362) -> (13.5904, 27.9102)
  line L59 (14.4519, 29.2362) -> (14.0733, 29.2362)
  line L60 (0, 47.1259) -> (44, 47.1259)
  line L61 (0, 10) -> (0, 47.1259)
  line L62 (44, 10) -> (0, 10)
  line L63 (44, 47.1259) -> (44, 10)
  curve K32
  curve K33
  curve K34
  curve K35
  dimension "d239" Text1-Height = 3
sketch "Sketch4" plane through (40, 0, 0) normal (1, 0, 0) x axis (0, 1, 0)
  line L1 (44.7318, 53.9359) -> (48.9918, 53.9359)
  line L2 (44.7318, 45.6759) -> (44.7318, 53.9359)
  line L3 (48.9918, 45.6759) -> (44.7318, 45.6759)
  line L4 (48.9918, 47.1259) -> (48.9918, 45.6759)
  line L5 (55.6118, 47.1259) -> (48.9918, 47.1259)
  line L6 (55.6118, 52.4859) -> (55.6118, 47.1259)
  line L7 (48.9918, 52.4859) -> (55.6118, 52.4859)
  line L8 (48.9918, 53.9359) -> (48.9918, 52.4859)
  circle C1 centre (44.7318, 49.8059) radius 0.85
  point P10 (44.7318, 49.8059)
  midpoint L2 P10
  dimension "d241" diameter C1 = 1.7 (= "filament_hole_width")
extrude "Extrude4" cut sketch "Sketch4" profile of L2 C1 no distance stored
sketch "Sketch15" plane through (-2, 0, 0) normal (-1, 0, 0) x axis (0, -1, 0)
  line L1 (-19.6118, 60) -> (-19.6118, 23.2332)
  line L2 (-39.6118, 60) -> (-19.6118, 60)
  line L3 (-39.6118, 52.6059) -> (-39.6118, 60)
  line L4 (-33.1118, 52.6059) -> (-39.6118, 52.6059)
  line L5 (-33.1118, 54.0559) -> (-33.1118, 52.6059)
  line L6 (-28.6118, 54.0559) -> (-33.1118, 54.0559)
  line L7 (-28.6118, 45.5559) -> (-28.6118, 54.0559)
  line L8 (-33.1118, 45.5559) -> (-28.6118, 45.5559)
  line L9 (-33.1118, 47.0059) -> (-33.1118, 45.5559)
  line L10 (-39.6118, 47.0059) -> (-33.1118, 47.0059)
  line L11 (-39.6118, 39.6118) -> (-39.6118, 47.0059)
  line L12 (-22.1725, 22.1725) -> (-39.6118, 39.6118)
  arc A1 centre (-21.1118, 23.2332) radius 1.5 clockwise from (-19.6118, 23.2332) to (-22.1725, 22.1725)
  circle C1 centre (-28.6118, 49.8059) radius 0.85
  point P16 (-28.6118, 49.8059)
  midpoint L7 P16
  dimension "d244" diameter C1 = 1.7 (= "filament_hole_width")
extrude "Extrude20" cut sketch "Sketch15" profile of L7 C1 no distance stored
sketch "Sketch9" plane through (44, 0, 0) normal (1, 0, 0) x axis (0, 1, 0)
  line L1 (49.1118, 47.0059) -> (55.6118, 47.0059)
  line L2 (49.1118, 45.5559) -> (49.1118, 47.0059)
  line L3 (44.6118, 45.5559) -> (49.1118, 45.5559)
  line L4 (44.6118, 54.0559) -> (44.6118, 45.5559)
  line L5 (49.1118, 54.0559) -> (44.6118, 54.0559)
  line L6 (49.1118, 52.6059) -> (49.1118, 54.0559)
  line L7 (55.6118, 52.6059) -> (49.1118, 52.6059)
  line L8 (55.6118, 60) -> (55.6118, 52.6059)
  line L9 (39.6118, 60) -> (55.6118, 60)
  line L10 (39.6118, 52.4859) -> (39.6118, 60)
  line L11 (32.9918, 52.4859) -> (39.6118, 52.4859)
  line L12 (32.9918, 53.9359) -> (32.9918, 52.4859)
  line L13 (28.7318, 53.9359) -> (32.9918, 53.9359)
  line L14 (28.7318, 45.6759) -> (28.7318, 53.9359)
  line L15 (32.9918, 45.6759) -> (28.7318, 45.6759)
  line L16 (32.9918, 47.1259) -> (32.9918, 45.6759)
  line L17 (39.6118, 47.1259) -> (32.9918, 47.1259)
  line L18 (39.6118, 10) -> (39.6118, 47.1259)
  line L19 (55.6118, 10) -> (39.6118, 10)
  line L20 (55.6118, 47.0059) -> (55.6118, 10)
  circle C1 centre (28.7318, 49.8059) radius 0.85
  circle C2 centre (44.6118, 49.8059) radius 0.85
  point P22 (28.7318, 49.8059)
  point P23 (44.6118, 49.8059)
  midpoint L14 P22
  midpoint L4 P23
  dimension "d247" diameter C1 = 1.7 (= "filament_hole_width")
  dimension "d250" diameter C2 = 1.7 (= "filament_hole_width")
extrude "Extrude12" cut sketch "Sketch9" profile of L4 L14 C1 C2 no distance stored
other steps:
create_component "CreateComponent1"
create_component "CreateComponent2"
create_component "CreateComponent3"
create_component "CreateComponent4"
named bodies: "Wall anchor part", "Base plate with slot"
